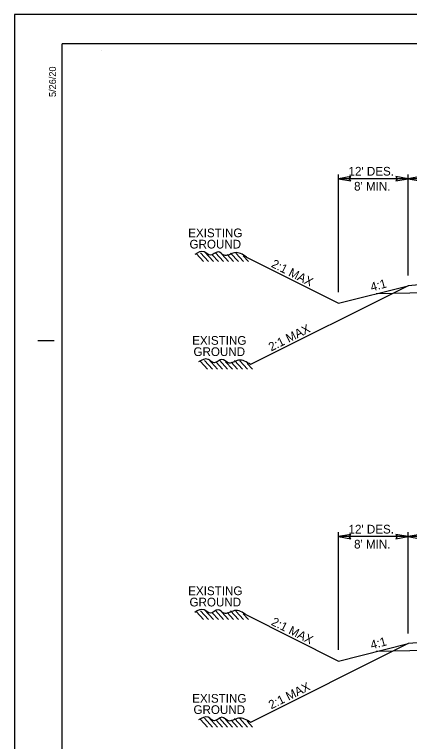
# Model space of a CAD drawing. Extents: x 1553884 to 1554215, y 810431 to 810779.
# Drawn here: x 1553901.4 to 1553946.8, y 810695.8 to 810779.4 of the extents above; entities that cross this region are included whole.
import ezdxf

# ---------------------------------------------------------------- set-up
doc = ezdxf.new("R2010")
doc.units = 0
for name, color, linetype in [('Old_Level_15', 7, 'Continuous'), ('Old_Level_2', 7, 'Continuous'), ('Prop Lane Arrow CELL', 7, 'Continuous'), ('Typical Arrow Superelevation CELL', 7, 'Continuous'), ('Typical Shoulder Slope CELL', 7, 'Continuous')]:
    doc.layers.add(name, color=color, linetype=linetype)

msp = doc.modelspace()

# ---------------------------------------------------------------- linework, layer by layer
at = {"layer": 'Old_Level_15'}
for points in [[(1553940.075, 810760.787), (1553938.669, 810760.545), (1553940.083, 810760.295), (1553939.904, 810760.545)], [(1553945.263, 810760.303), (1553946.669, 810760.545), (1553945.256, 810760.795), (1553945.435, 810760.545)], [(1553948.075, 810760.787), (1553946.669, 810760.545), (1553948.083, 810760.295), (1553947.904, 810760.545)], [(1553940.075, 810719.628), (1553938.669, 810719.385), (1553940.083, 810719.135), (1553939.904, 810719.385)], [(1553945.263, 810719.143), (1553946.669, 810719.385), (1553945.256, 810719.635), (1553945.435, 810719.385)], [(1553948.075, 810719.628), (1553946.669, 810719.385), (1553948.083, 810719.135), (1553947.904, 810719.385)]]:
    msp.add_lwpolyline(points, close=True, dxfattribs=at)
at = {"layer": 'Old_Level_2'}
for p, q in [((1553906.821, 810617.805), (1553906.825, 810776.052)), ((1554154.325, 810776.052), (1553906.825, 810776.052)), ((1553911.319, 810775.307), (1553911.319, 810775.307)), ((1553904.051, 810741.928), (1553905.928, 810741.932))]:
    msp.add_line(p, q, dxfattribs=at)
at = {"layer": 'Prop Lane Arrow CELL'}
for p, q in [((1554156.35, 810779.427), (1553901.353, 810779.427)), ((1553901.353, 810779.427), (1553901.353, 810614.43))]:
    msp.add_line(p, q, dxfattribs=at)
at = {"layer": 'Typical Shoulder Slope CELL'}
for p, q in [((1553938.669, 810747.519), (1553938.669, 810761.045)), ((1553946.669, 810760.545), (1553938.669, 810760.545)), ((1553946.669, 810749.404), (1553946.669, 810761.045)), ((1553950.669, 810760.545), (1553946.669, 810760.545)), ((1553922.309, 810751.895), (1553923.107, 810751.009)), ((1553922.772, 810752.021), (1553923.683, 810751.009)), ((1553923.237, 810752.144), (1553924.259, 810751.009)), ((1553924.125, 810751.798), (1553924.835, 810751.009)), ((1553924.486, 810752.037), (1553925.411, 810751.009)), ((1553925.211, 810751.871), (1553925.987, 810751.009)), ((1553925.835, 810751.818), (1553926.563, 810751.009)), ((1553926.245, 810752.003), (1553927.139, 810751.009)), ((1553926.84, 810751.981), (1553927.715, 810751.009)), ((1553927.689, 810751.677), (1553928.291, 810751.009)), ((1553928.076, 810751.539), (1553938.669, 810746.242)), ((1553946.669, 810748.242), (1553928.534, 810739.175)), ((1553938.669, 810746.242), (1553946.669, 810748.242)), ((1553950.618, 810748.558), (1553946.669, 810748.242)), ((1553949.512, 810747.453), (1553942.989, 810747.322)), ((1553923.229, 810739.657), (1553924.14, 810738.644)), ((1553923.695, 810739.78), (1553924.716, 810738.644)), ((1553924.943, 810739.673), (1553925.868, 810738.644)), ((1553926.702, 810739.638), (1553927.596, 810738.644)), ((1553922.767, 810739.531), (1553923.564, 810738.644)), ((1553924.582, 810739.433), (1553925.292, 810738.644)), ((1553925.669, 810739.507), (1553926.444, 810738.644)), ((1553926.292, 810739.454), (1553927.02, 810738.644)), ((1553927.298, 810739.617), (1553928.172, 810738.644)), ((1553928.147, 810739.313), (1553928.748, 810738.644)), ((1553938.669, 810706.359), (1553938.669, 810719.885)), ((1553946.669, 810708.244), (1553946.669, 810719.885)), ((1553946.669, 810719.385), (1553938.669, 810719.385)), ((1553950.669, 810719.385), (1553946.669, 810719.385)), ((1553922.309, 810710.735), (1553923.107, 810709.849)), ((1553922.772, 810710.861), (1553923.683, 810709.849)), ((1553923.237, 810710.984), (1553924.259, 810709.849)), ((1553924.125, 810710.638), (1553924.835, 810709.849)), ((1553924.486, 810710.877), (1553925.411, 810709.849)), ((1553925.211, 810710.711), (1553925.987, 810709.849)), ((1553925.835, 810710.658), (1553926.563, 810709.849)), ((1553926.245, 810710.843), (1553927.139, 810709.849)), ((1553926.84, 810710.821), (1553927.715, 810709.849)), ((1553927.689, 810710.517), (1553928.291, 810709.849)), ((1553928.076, 810710.379), (1553938.669, 810705.082)), ((1553946.669, 810707.082), (1553928.534, 810698.015)), ((1553938.669, 810705.082), (1553946.669, 810707.082)), ((1553950.618, 810707.398), (1553946.669, 810707.082)), ((1553949.512, 810706.293), (1553942.989, 810706.162)), ((1553922.767, 810698.371), (1553923.564, 810697.484)), ((1553923.229, 810698.497), (1553924.14, 810697.484)), ((1553923.695, 810698.62), (1553924.716, 810697.484)), ((1553924.582, 810698.273), (1553925.292, 810697.484)), ((1553924.943, 810698.513), (1553925.868, 810697.484)), ((1553925.669, 810698.347), (1553926.444, 810697.484)), ((1553926.292, 810698.294), (1553927.02, 810697.484)), ((1553926.702, 810698.478), (1553927.596, 810697.484)), ((1553927.298, 810698.457), (1553928.172, 810697.484)), ((1553928.147, 810698.153), (1553928.748, 810697.484))]:
    msp.add_line(p, q, dxfattribs=at)
for points in [[(1553928.076, 810751.539), (1553926.682, 810752.038), (1553925.487, 810751.738), (1553924.79, 810752.137), (1553923.894, 810751.738), (1553923.196, 810752.137), (1553922.101, 810751.838)], [(1553928.534, 810739.175), (1553927.14, 810739.673), (1553925.945, 810739.374), (1553925.247, 810739.773), (1553924.351, 810739.374), (1553923.654, 810739.773), (1553922.558, 810739.474)], [(1553928.076, 810710.379), (1553926.682, 810710.878), (1553925.487, 810710.578), (1553924.79, 810710.977), (1553923.894, 810710.578), (1553923.196, 810710.977), (1553922.101, 810710.678)], [(1553928.534, 810698.015), (1553927.14, 810698.513), (1553925.945, 810698.214), (1553925.247, 810698.613), (1553924.351, 810698.214), (1553923.654, 810698.613), (1553922.558, 810698.314)]]:
    msp.add_spline(points, degree=3, dxfattribs=at)

# ---------------------------------------------------------------- texts
at = {"layer": 'Old_Level_2'}
msp.add_text('5/26/20', height=0.7875, rotation=90, dxfattribs=at).set_placement((1553906.123, 810769.942))
at = {"layer": 'Typical Arrow Superelevation CELL'}
for s, p in [("12' DES.", (1553939.817, 810760.907)), ("8' MIN.", (1553940.457, 810759.183)), ('EXISTING', (1553921.356, 810753.817)), ('GROUND', (1553921.505, 810752.522)), ('EXISTING', (1553921.813, 810741.452)), ('GROUND', (1553921.963, 810740.158)), ("12' DES.", (1553939.817, 810719.747)), ("8' MIN.", (1553940.457, 810718.023)), ('EXISTING', (1553921.356, 810712.657)), ('GROUND', (1553921.505, 810711.362)), ('EXISTING', (1553921.813, 810700.292)), ('GROUND', (1553921.963, 810698.998))]:
    msp.add_text(s, height=1, dxfattribs=at).set_placement(p)
for s, rotation, p in [('2:1 MAX', 333.43495, (1553930.833, 810750.434)), ('4:1', 14.94701, (1553942.487, 810747.583)), ('2:1 MAX', 26.56505, (1553930.918, 810740.676)), ('2:1 MAX', 333.43495, (1553930.833, 810709.274)), ('4:1', 14.94701, (1553942.487, 810706.423)), ('2:1 MAX', 26.56505, (1553930.918, 810699.516))]:
    msp.add_text(s, height=1, rotation=rotation, dxfattribs=at).set_placement(p)

doc.saveas('drawing.dxf')
